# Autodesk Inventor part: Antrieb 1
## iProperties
Created: 2004-11
Part Number: Antrieb 1
Document SubType Name: Modeling
Designer: PALME
Manufacturer: Standard
Standards Organization: Custom
Author: PALME
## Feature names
1. Extrusion1
2. Extrusion2
3. Extrusion3
